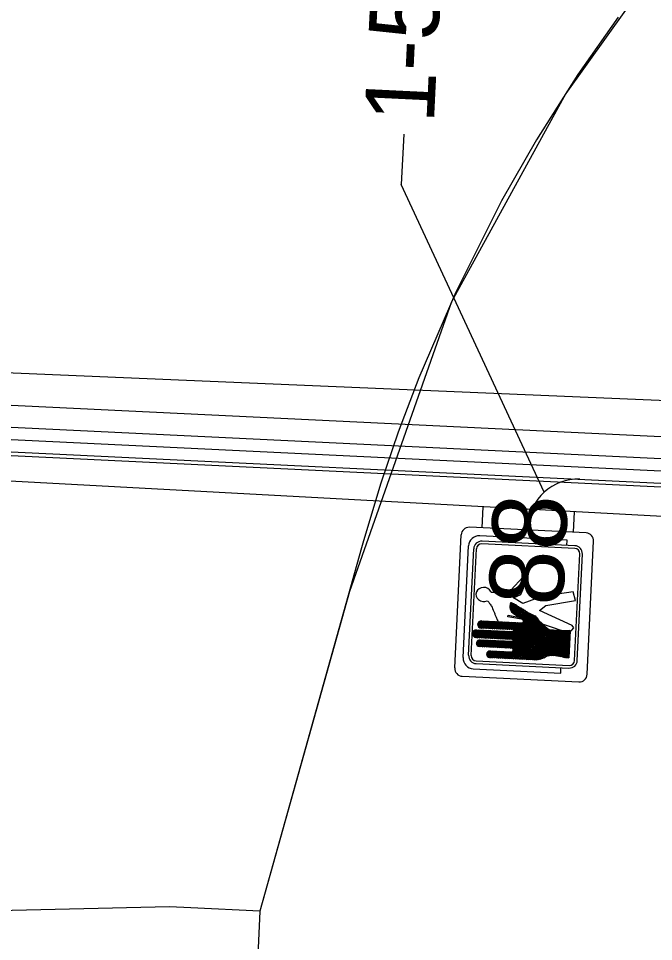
# Model space of a CAD drawing. Extents: x 590069 to 611209, y 383148 to 419683.
# Drawn here: x 610716.2 to 610760.9, y 419083.1 to 419148.2 of the extents above; entities that cross this region are included whole.
import ezdxf

# ---------------------------------------------------------------- set-up
doc = ezdxf.new("R2010")
doc.units = 0
doc.layers.add('G-No Plot-Stamp-1', color=7, linetype='Continuous')
doc.layers.add('T_Drafting', color=7, linetype='Continuous')

msp = doc.modelspace()

# ---------------------------------------------------------------- linework, layer by layer
at = {"layer": 'G-No Plot-Stamp-1'}
for p, q in [((610758.429, 419148.274), (610755.6, 419144.221)), ((610755.6, 419144.221), (610752.688, 419139.621)), ((610752.688, 419139.621), (610750.219, 419135.302)), ((610750.219, 419135.302), (610746.986, 419128.882)), ((610746.986, 419128.882), (610744.379, 419122.832)), ((610744.379, 419122.832), (610742.929, 419118.988)), ((610742.929, 419118.988), (610741.715, 419115.402)), ((610741.715, 419115.402), (610740.493, 419111.332)), ((610740.493, 419111.332), (610740.355, 419110.835)), ((610740.355, 419110.835), (610733.188, 419085.224)), ((610733.188, 419085.224), (610721.902, 418847.252))]:
    msp.add_line(p, q, dxfattribs=at)
msp.add_lwpolyline([(610760.433, 419150.848), (610754.751, 419142.88), (610746.684, 419128.182), (610739.494, 419107.758), (610733.188, 419085.224), (610728.322, 419085.466), (610726.823, 419085.531), (610671.434, 419084.226), (610669.935, 419084.291), (610669.407, 419084.314), (610482.982, 419253.329)], dxfattribs=at)
at = {"layer": 'T_Drafting'}
for p, q in [((610743.323, 419140.002), (610743.152, 419136.461)), ((610753.219, 419114.771), (610743.152, 419136.461)), ((610462.242, 419133.932), (610811.933, 419119.098)), ((610469.734, 419131.223), (610794.828, 419115.543)), ((610811.511, 419110.358), (610462.016, 419129.248)), ((610497.379, 419129.014), (610795.24, 419114.647)), ((610801.686, 419116.731), (610576.826, 419127.576)), ((610802.381, 419113.156), (610575.712, 419124.088)), ((610675.302, 419119.556), (610802.475, 419113.422)), ((610748.847, 419112.247), (610748.919, 419113.741)), ((610755.28, 419111.937), (610755.35, 419113.393)), ((610746.915, 419102.377), (610747.368, 419111.754)), ((610756.172, 419111.894), (610747.955, 419112.29)), ((610752.063, 419112.092), (610752.076, 419112.349)), ((610754.838, 419111.394), (610748.675, 419111.691)), ((610755.371, 419110.805), (610748.834, 419111.12)), ((610755.38, 419110.992), (610748.844, 419111.307)), ((610754.819, 419111.019), (610754.838, 419111.394)), ((610756.253, 419101.927), (610756.705, 419111.304)), ((610747.512, 419103.1), (610747.892, 419110.977)), ((610747.894, 419103.27), (610748.256, 419110.772)), ((610748.081, 419103.261), (610748.443, 419110.763)), ((610755.364, 419102.909), (610755.726, 419110.411)), ((610755.551, 419102.9), (610755.913, 419110.402)), ((610750.828, 419106.637), (610751.117, 419106.874)), ((610754.332, 419103.188), (610750.83, 419106.674)), ((610750.834, 419106.756), (610751.034, 419106.92)), ((610754.492, 419103.154), (610750.836, 419106.793)), ((610750.845, 419106.536), (610751.205, 419106.831)), ((610751.424, 419105.958), (610750.846, 419106.533)), ((610750.85, 419106.884), (610750.95, 419106.966)), ((610754.665, 419103.106), (610750.853, 419106.901)), ((610750.875, 419106.446), (610751.284, 419106.782)), ((610754.801, 419103.095), (610750.893, 419106.986)), ((610750.91, 419106.36), (610751.361, 419106.73)), ((610750.956, 419106.284), (610751.44, 419106.68)), ((610751.023, 419106.224), (610751.523, 419106.634)), ((610751.098, 419106.171), (610751.607, 419106.588)), ((610754.933, 419103.089), (610751.147, 419106.858)), ((610751.178, 419106.121), (610751.688, 419106.54)), ((610754.96, 419103.187), (610751.468, 419106.664)), ((610750.491, 419104.412), (610752.523, 419106.078)), ((610750.623, 419104.405), (610752.595, 419106.022)), ((610750.755, 419104.399), (610752.662, 419105.963)), ((610750.887, 419104.393), (610752.726, 419105.901)), ((610751.053, 419106.202), (610750.917, 419106.337)), ((610751.068, 419104.999), (610752.432, 419106.118)), ((610751.25, 419106.066), (610751.768, 419106.491)), ((610751.328, 419106.015), (610751.848, 419106.441)), ((610751.408, 419105.966), (610751.924, 419106.389)), ((610751.494, 419105.922), (610751.999, 419106.336)), ((610751.566, 419105.867), (610752.078, 419106.286)), ((610751.64, 419105.813), (610752.159, 419106.238)), ((610751.708, 419105.754), (610752.244, 419106.193)), ((610754.966, 419103.307), (610751.766, 419106.492)), ((610751.776, 419105.695), (610752.335, 419106.153)), ((610754.971, 419103.427), (610752.129, 419106.256)), ((610754.977, 419103.546), (610752.374, 419106.138)), ((610748.533, 419105.443), (610748.833, 419105.689)), ((610748.814, 419105.178), (610748.534, 419105.457)), ((610748.552, 419105.344), (610748.965, 419105.683)), ((610748.946, 419105.172), (610748.564, 419105.552)), ((610748.601, 419105.269), (610749.097, 419105.677)), ((610749.078, 419105.166), (610748.621, 419105.621)), ((610748.673, 419105.214), (610749.229, 419105.67)), ((610749.21, 419105.16), (610748.699, 419105.668)), ((610748.772, 419105.181), (610749.362, 419105.664)), ((610749.342, 419105.153), (610748.803, 419105.69)), ((610748.821, 419105.69), (610751.681, 419105.555)), ((610748.904, 419105.174), (610749.494, 419105.658)), ((610749.473, 419105.147), (610748.934, 419105.684)), ((610749.036, 419105.168), (610749.626, 419105.652)), ((610749.605, 419105.141), (610749.066, 419105.678)), ((610749.168, 419105.162), (610749.758, 419105.645)), ((610749.737, 419105.135), (610749.198, 419105.672)), ((610749.3, 419105.155), (610749.89, 419105.639)), ((610749.869, 419105.129), (610749.33, 419105.666)), ((610749.433, 419105.149), (610750.023, 419105.633)), ((610750.001, 419105.122), (610749.462, 419105.659)), ((610749.565, 419105.143), (610750.155, 419105.627)), ((610750.133, 419105.116), (610749.593, 419105.653)), ((610749.697, 419105.137), (610750.287, 419105.62)), ((610750.265, 419105.11), (610749.725, 419105.647)), ((610749.829, 419105.13), (610750.419, 419105.614)), ((610750.397, 419105.104), (610749.857, 419105.641)), ((610749.962, 419105.124), (610750.552, 419105.608)), ((610750.529, 419105.098), (610749.989, 419105.634)), ((610750.094, 419105.118), (610750.684, 419105.602)), ((610750.66, 419105.091), (610750.121, 419105.628)), ((610750.226, 419105.112), (610750.816, 419105.595)), ((610750.792, 419105.085), (610750.253, 419105.622)), ((610750.358, 419105.106), (610750.948, 419105.589)), ((610750.924, 419105.079), (610750.385, 419105.616)), ((610750.49, 419105.099), (610751.08, 419105.583)), ((610750.503, 419103.046), (610753.265, 419105.311)), ((610753.105, 419103.033), (610750.517, 419105.61)), ((610750.573, 419103.791), (610752.889, 419105.69)), ((610750.623, 419105.093), (610751.213, 419105.577)), ((610750.636, 419103.04), (610753.333, 419105.252)), ((610753.188, 419103.076), (610750.649, 419105.603)), ((610750.705, 419103.785), (610752.953, 419105.628)), ((610750.755, 419105.087), (610751.345, 419105.571)), ((610753.27, 419103.119), (610750.781, 419105.597)), ((610750.838, 419103.779), (610753.017, 419105.566)), ((610750.887, 419105.081), (610751.477, 419105.564)), ((610753.353, 419103.161), (610750.913, 419105.591)), ((610750.959, 419103.764), (610753.079, 419105.502)), ((610751.01, 419104.379), (610752.78, 419105.83)), ((610751.016, 419105.072), (610751.609, 419105.558)), ((610751.027, 419103.705), (610753.141, 419105.438)), ((610751.039, 419103.601), (610753.202, 419105.374)), ((610751.04, 419104.289), (610752.831, 419105.757)), ((610753.437, 419103.203), (610751.044, 419105.585)), ((610753.532, 419103.234), (610751.176, 419105.578)), ((610753.65, 419103.241), (610751.308, 419105.572)), ((610753.77, 419103.247), (610751.44, 419105.566)), ((610753.894, 419103.248), (610751.572, 419105.56)), ((610754.027, 419103.241), (610751.686, 419105.572)), ((610754.182, 419103.212), (610751.772, 419105.611)), ((610748.154, 419104.788), (610748.481, 419105.056)), ((610748.484, 419104.506), (610748.158, 419104.831)), ((610748.331, 419104.534), (610748.171, 419104.692)), ((610748.173, 419104.689), (610748.613, 419105.05)), ((610748.616, 419104.5), (610748.193, 419104.921)), ((610748.22, 419104.613), (610748.745, 419105.044)), ((610748.224, 419104.96), (610748.285, 419105.011)), ((610748.748, 419104.494), (610748.252, 419104.987)), ((610748.289, 419104.555), (610748.877, 419105.038)), ((610748.88, 419104.487), (610748.331, 419105.034)), ((610748.382, 419104.517), (610749.01, 419105.032)), ((610749.012, 419104.481), (610748.433, 419105.057)), ((610748.45, 419105.058), (610750.982, 419104.939)), ((610748.507, 419104.505), (610749.142, 419105.025)), ((610749.143, 419104.475), (610748.563, 419105.053)), ((610748.639, 419104.499), (610749.274, 419105.019)), ((610749.275, 419104.469), (610748.695, 419105.046)), ((610748.772, 419104.493), (610749.406, 419105.013)), ((610751.001, 419105.075), (610748.779, 419105.18)), ((610749.407, 419104.463), (610748.827, 419105.04)), ((610748.904, 419104.486), (610749.538, 419105.007)), ((610749.539, 419104.456), (610748.959, 419105.034)), ((610749.036, 419104.48), (610749.671, 419105)), ((610749.671, 419104.45), (610749.091, 419105.028)), ((610749.168, 419104.474), (610749.803, 419104.994)), ((610749.803, 419104.444), (610749.223, 419105.021)), ((610749.301, 419104.468), (610749.935, 419104.988)), ((610749.935, 419104.438), (610749.355, 419105.015)), ((610749.433, 419104.461), (610750.067, 419104.982)), ((610750.067, 419104.432), (610749.487, 419105.009)), ((610749.565, 419104.455), (610750.2, 419104.975)), ((610750.199, 419104.425), (610749.618, 419105.003)), ((610749.697, 419104.449), (610750.332, 419104.969)), ((610750.33, 419104.419), (610749.75, 419104.997)), ((610749.829, 419104.443), (610750.464, 419104.963)), ((610750.462, 419104.413), (610749.882, 419104.99)), ((610749.962, 419104.436), (610750.596, 419104.957)), ((610750.594, 419104.407), (610750.014, 419104.984)), ((610750.094, 419104.43), (610750.728, 419104.951)), ((610750.726, 419104.4), (610750.146, 419104.978)), ((610750.226, 419104.424), (610750.861, 419104.944)), ((610750.858, 419104.394), (610750.278, 419104.972)), ((610750.358, 419104.418), (610750.99, 419104.936)), ((610750.991, 419104.386), (610750.41, 419104.966)), ((610752.556, 419102.954), (610750.542, 419104.959)), ((610752.684, 419102.952), (610750.674, 419104.953)), ((610750.768, 419103.034), (610753.407, 419105.198)), ((610752.796, 419102.965), (610750.806, 419104.947)), ((610750.9, 419103.028), (610753.477, 419105.141)), ((610752.909, 419102.978), (610750.937, 419104.941)), ((610751.032, 419103.022), (610753.561, 419105.095)), ((610753.015, 419102.997), (610751.046, 419104.957)), ((610751.164, 419103.015), (610753.657, 419105.059)), ((610751.297, 419103.009), (610753.794, 419105.056)), ((610751.429, 419103.003), (610753.919, 419105.045)), ((610751.561, 419102.997), (610754.052, 419105.039)), ((610751.693, 419102.99), (610754.191, 419105.038)), ((610751.826, 419102.984), (610754.324, 419105.032)), ((610751.958, 419102.978), (610754.456, 419105.026)), ((610752.09, 419102.972), (610754.588, 419105.02)), ((610752.222, 419102.965), (610754.721, 419105.014)), ((610752.354, 419102.959), (610754.859, 419105.013)), ((610752.487, 419102.954), (610755, 419105.014)), ((610752.625, 419102.952), (610755.042, 419104.934)), ((610752.779, 419102.963), (610755.036, 419104.814)), ((610752.942, 419102.982), (610755.031, 419104.695)), ((610753.209, 419103.086), (610755.025, 419104.576)), ((610754.983, 419103.666), (610753.525, 419105.117)), ((610754.988, 419103.785), (610753.709, 419105.059)), ((610754.994, 419103.905), (610753.842, 419105.051)), ((610754.999, 419104.024), (610753.977, 419105.041)), ((610755.005, 419104.144), (610754.106, 419105.038)), ((610755.011, 419104.263), (610754.234, 419105.037)), ((610755.016, 419104.383), (610754.366, 419105.03)), ((610755.022, 419104.502), (610754.498, 419105.024)), ((610755.027, 419104.622), (610754.629, 419105.018)), ((610755.033, 419104.741), (610754.759, 419105.014)), ((610755.039, 419104.861), (610754.886, 419105.013)), ((610755.045, 419105.003), (610754.956, 419103.098)), ((610755.044, 419104.98), (610755.011, 419105.013)), ((610755.048, 419105.012), (610755.045, 419105.003)), ((610750.981, 419104.388), (610748.431, 419104.509)), ((610748.44, 419104.106), (610748.745, 419104.356)), ((610748.738, 419103.878), (610748.445, 419104.169)), ((610748.583, 419103.907), (610748.46, 419104.03)), ((610748.468, 419104.014), (610748.877, 419104.35)), ((610748.87, 419103.872), (610748.485, 419104.255)), ((610748.492, 419104.264), (610748.566, 419104.324)), ((610748.524, 419103.945), (610749.01, 419104.344)), ((610749.002, 419103.865), (610748.551, 419104.315)), ((610748.605, 419103.898), (610749.142, 419104.338)), ((610749.134, 419103.859), (610748.639, 419104.351)), ((610748.704, 419104.358), (610750.962, 419104.252)), ((610748.722, 419103.879), (610749.274, 419104.331)), ((610749.266, 419103.853), (610748.761, 419104.355)), ((610748.854, 419103.872), (610749.406, 419104.325)), ((610749.397, 419103.847), (610748.893, 419104.349)), ((610748.986, 419103.866), (610749.539, 419104.319)), ((610749.529, 419103.841), (610749.025, 419104.343)), ((610749.119, 419103.86), (610749.671, 419104.313)), ((610749.661, 419103.834), (610749.157, 419104.337)), ((610749.251, 419103.854), (610749.803, 419104.306)), ((610749.793, 419103.828), (610749.288, 419104.331)), ((610749.383, 419103.848), (610749.935, 419104.3)), ((610749.925, 419103.822), (610749.42, 419104.324)), ((610749.515, 419103.841), (610750.067, 419104.294)), ((610750.057, 419103.816), (610749.552, 419104.318)), ((610749.648, 419103.835), (610750.2, 419104.288)), ((610750.189, 419103.81), (610749.684, 419104.312)), ((610749.78, 419103.829), (610750.332, 419104.282)), ((610750.321, 419103.803), (610749.816, 419104.306)), ((610749.912, 419103.823), (610750.464, 419104.275)), ((610750.453, 419103.797), (610749.948, 419104.3)), ((610750.044, 419103.816), (610750.596, 419104.269)), ((610750.585, 419103.791), (610750.08, 419104.293)), ((610750.176, 419103.81), (610750.729, 419104.263)), ((610750.716, 419103.785), (610750.212, 419104.287)), ((610750.309, 419103.804), (610750.861, 419104.257)), ((610750.848, 419103.779), (610750.344, 419104.281)), ((610750.441, 419103.798), (610751, 419104.256)), ((610751.769, 419102.987), (610750.475, 419104.275)), ((610751.901, 419102.981), (610750.607, 419104.269)), ((610752.033, 419102.974), (610750.739, 419104.262)), ((610752.165, 419102.968), (610750.871, 419104.256)), ((610752.297, 419102.962), (610750.998, 419104.255)), ((610752.429, 419102.956), (610751.046, 419104.332)), ((610753.527, 419103.233), (610755.02, 419104.457)), ((610753.679, 419103.243), (610755.014, 419104.337)), ((610753.825, 419103.248), (610755.009, 419104.218)), ((610753.962, 419103.246), (610755.003, 419104.099)), ((610754.085, 419103.232), (610754.997, 419103.98)), ((610750.903, 419103.776), (610748.675, 419103.881)), ((610749.159, 419103.32), (610749.469, 419103.574)), ((610749.395, 419103.099), (610749.159, 419103.334)), ((610749.527, 419103.092), (610749.182, 419103.436)), ((610749.188, 419103.229), (610749.601, 419103.568)), ((610749.202, 419103.47), (610749.298, 419103.549)), ((610749.659, 419103.086), (610749.236, 419103.507)), ((610749.245, 419103.161), (610749.733, 419103.561)), ((610749.791, 419103.08), (610749.313, 419103.555)), ((610749.328, 419103.114), (610749.865, 419103.555)), ((610749.923, 419103.074), (610749.418, 419103.576)), ((610749.423, 419103.576), (610750.891, 419103.507)), ((610749.446, 419103.096), (610749.998, 419103.549)), ((610750.055, 419103.068), (610749.55, 419103.57)), ((610749.578, 419103.09), (610750.13, 419103.543)), ((610750.186, 419103.061), (610749.682, 419103.564)), ((610749.71, 419103.084), (610750.262, 419103.537)), ((610750.318, 419103.055), (610749.814, 419103.558)), ((610749.842, 419103.078), (610750.394, 419103.53)), ((610750.45, 419103.049), (610749.946, 419103.551)), ((610749.974, 419103.071), (610750.527, 419103.524)), ((610750.582, 419103.043), (610750.077, 419103.545)), ((610750.107, 419103.065), (610750.659, 419103.518)), ((610750.714, 419103.037), (610750.209, 419103.539)), ((610750.239, 419103.059), (610750.791, 419103.512)), ((610750.846, 419103.03), (610750.341, 419103.533)), ((610750.371, 419103.053), (610750.928, 419103.509)), ((610750.978, 419103.024), (610750.473, 419103.527)), ((610751.11, 419103.018), (610750.605, 419103.52)), ((610751.242, 419103.012), (610750.737, 419103.514)), ((610751.374, 419103.005), (610750.869, 419103.508)), ((610751.505, 419102.999), (610750.976, 419103.526)), ((610751.637, 419102.993), (610751.036, 419103.592)), ((610754.197, 419103.209), (610754.992, 419103.861)), ((610754.314, 419103.19), (610754.986, 419103.741)), ((610754.431, 419103.172), (610754.981, 419103.622)), ((610754.531, 419103.139), (610754.975, 419103.503)), ((610754.635, 419103.109), (610754.969, 419103.384)), ((610754.761, 419103.098), (610754.964, 419103.265)), ((610748.427, 419102.68), (610754.964, 419102.365)), ((610748.436, 419102.868), (610754.973, 419102.552)), ((610752.473, 419102.954), (610749.394, 419103.099)), ((610754.892, 419103.091), (610754.958, 419103.145)), ((610754.956, 419103.098), (610754.944, 419103.089)), ((610748.223, 419102.314), (610754.385, 419102.017)), ((610754.385, 419102.017), (610754.403, 419102.392)), ((610747.448, 419101.787), (610755.665, 419101.391))]:
    msp.add_line(p, q, dxfattribs=at)
msp.add_lwpolyline([(610750.076, 419105.429), (610751.748, 419105.261), (610751.772, 419105.781), (610750.67, 419105.968), (610750.68, 419106.087), (610751.657, 419105.91), (610751.823, 419105.902), (610754.889, 419104.866), (610755.01, 419104.86), (610755.3, 419105.203), (610755.185, 419105.359), (610752.88, 419106.415), (610753.338, 419106.777), (610755.435, 419107.131), (610755.266, 419107.729), (610753.049, 419107.422), (610751.719, 419106.922), (610751.07, 419107.323), (610751.567, 419107.561), (610752.025, 419108.582), (610751.746, 419108.8), (610750.871, 419107.85), (610749.811, 419107.643), (610749.659, 419107.692), (610749.491, 419107.702), (610749.465, 419107.755)], dxfattribs=at)
msp.add_arc((610755.572, 419112.18), 3.5, 87.23861, 177.23861, dxfattribs=at)
for centre, major_axis, ratio, start_param, end_param in [((610747.928, 419111.727), (-0.027, -0.563), 0.995724, 3.141593, 4.712389), ((610756.145, 419111.331), (0.027, 0.563), 0.995724, 4.712389, 6.283185), ((610748.639, 419110.941), (-0.036, -0.75), 0.995724, 3.141593, 4.712389), ((610748.816, 419110.745), (-0.027, -0.563), 0.995724, 3.141593, 4.712389), ((610748.816, 419110.745), (-0.018, -0.375), 0.995724, 3.141593, 4.712389), ((610755.353, 419110.429), (0.018, 0.375), 0.995724, 4.712389, 6.283185), ((610755.353, 419110.429), (0.027, 0.563), 0.995724, 4.712389, 6.283185), ((610748.962, 419107.557), (0.55, -0.027), 0.903865, 0.463156, 5.216339), ((610748.816, 419105.434), (0.283, -0.014), 0.903865, 1.597842, 4.623315), ((610748.458, 419104.783), (0.304, -0.015), 0.903865, 1.640121, 4.665593), ((610750.991, 419105.006), (0.0773, -0.0037), 0.903865, 4.624552, 7.766145), ((610748.705, 419104.119), (0.265, -0.013), 0.903865, 1.618611, 4.644084), ((610750.971, 419104.32), (0.0762, -0.0037), 0.903865, 4.633755, 7.775348), ((610748.455, 419103.243), (-0.027, -0.563), 0.995724, 4.712389, 6.283185), ((610748.455, 419103.243), (-0.018, -0.375), 0.995724, 4.712389, 6.283185), ((610749.424, 419103.337), (0.265, -0.013), 0.903865, 1.618611, 4.644084), ((610750.897, 419103.641), (0.149, -0.007), 0.903865, 4.713646, 7.855239), ((610748.259, 419103.064), (-0.036, -0.75), 0.995724, 4.712389, 6.283185), ((610754.991, 419102.927), (-0.027, -0.563), 0.995724, 0, 1.570796), ((610754.991, 419102.927), (-0.018, -0.375), 0.995724, 0, 1.570796), ((610747.476, 419102.35), (-0.027, -0.563), 0.995724, 4.712389, 6.283185), ((610755.693, 419101.954), (-0.027, -0.563), 0.995724, 0, 1.570796)]:
    msp.add_ellipse(centre, major_axis=major_axis, ratio=ratio, start_param=start_param, end_param=end_param, dxfattribs=at)
for points in [[(610749.207, 419107.109), (610749.293, 419107.047), (610749.336, 419106.966), (610749.408, 419106.866), (610749.49, 419106.754), (610749.672, 419106.346), (610749.754, 419106.15), (610749.826, 419105.959), (610749.946, 419105.703), (610749.989, 419105.579), (610750.076, 419105.429)], [(610751.681, 419105.555), (610751.687, 419105.574), (610751.746, 419105.597), (610751.792, 419105.628), (610751.8, 419105.647), (610751.794, 419105.68), (610751.766, 419105.702), (610751.696, 419105.765), (610751.639, 419105.814), (610751.597, 419105.842), (610751.562, 419105.87), (610751.498, 419105.92), (610751.441, 419105.949), (610751.362, 419105.992), (610751.32, 419106.021), (610751.242, 419106.071), (610751.171, 419106.126), (610751.1, 419106.17), (610751.029, 419106.219), (610750.98, 419106.262), (610750.924, 419106.323), (610750.898, 419106.397), (610750.878, 419106.438), (610750.859, 419106.498), (610750.839, 419106.552), (610750.828, 419106.633), (610750.831, 419106.698), (610750.835, 419106.784), (610750.846, 419106.863), (610750.865, 419106.955), (610750.882, 419106.98), (610750.903, 419106.985), (610750.996, 419106.942), (610751.047, 419106.913), (610751.097, 419106.884), (610751.154, 419106.855), (610751.19, 419106.84), (610751.282, 419106.783), (610751.41, 419106.698), (610751.617, 419106.582), (610751.852, 419106.438), (610752.015, 419106.325), (610752.122, 419106.26), (610752.222, 419106.203), (610752.302, 419106.168), (610752.342, 419106.15), (610752.516, 419106.083), (610752.636, 419105.985), (610752.72, 419105.908), (610752.803, 419105.799), (610752.851, 419105.73), (610753.033, 419105.549), (610753.187, 419105.39), (610753.292, 419105.286), (610753.412, 419105.194), (610753.465, 419105.149), (610753.539, 419105.109), (610753.611, 419105.066), (610753.772, 419105.058), (610753.916, 419105.045), (610754.048, 419105.039), (610754.223, 419105.037), (610754.391, 419105.029), (610754.661, 419105.016), (610754.88, 419105.013), (610754.961, 419105.015), (610755.02, 419105.013), (610755.048, 419105.011)], [(610754.944, 419103.089), (610754.826, 419103.094), (610754.63, 419103.11), (610754.428, 419103.172), (610754.195, 419103.21), (610754.064, 419103.236), (610753.809, 419103.248), (610753.596, 419103.238), (610753.486, 419103.223), (610753.298, 419103.133), (610753.11, 419103.036), (610752.954, 419102.984), (610752.792, 419102.965), (610752.667, 419102.951), (610752.587, 419102.954), (610752.473, 419102.954)]]:
    msp.add_spline(points, degree=3, dxfattribs=at)

# ---------------------------------------------------------------- texts
for s, height, rotation, p in [('1-5c/#14', 4.9, 87.23861, (610745.447, 419140.735)), ('88', 5.235, 87.31033, (610754.528, 419106.696))]:
    msp.add_text(s, height=height, rotation=rotation, dxfattribs=at).set_placement(p)

doc.saveas('drawing.dxf')
